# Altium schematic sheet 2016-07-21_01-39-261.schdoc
size 367 x 190 mm; SheetNumber: 1; SheetTotal: 1
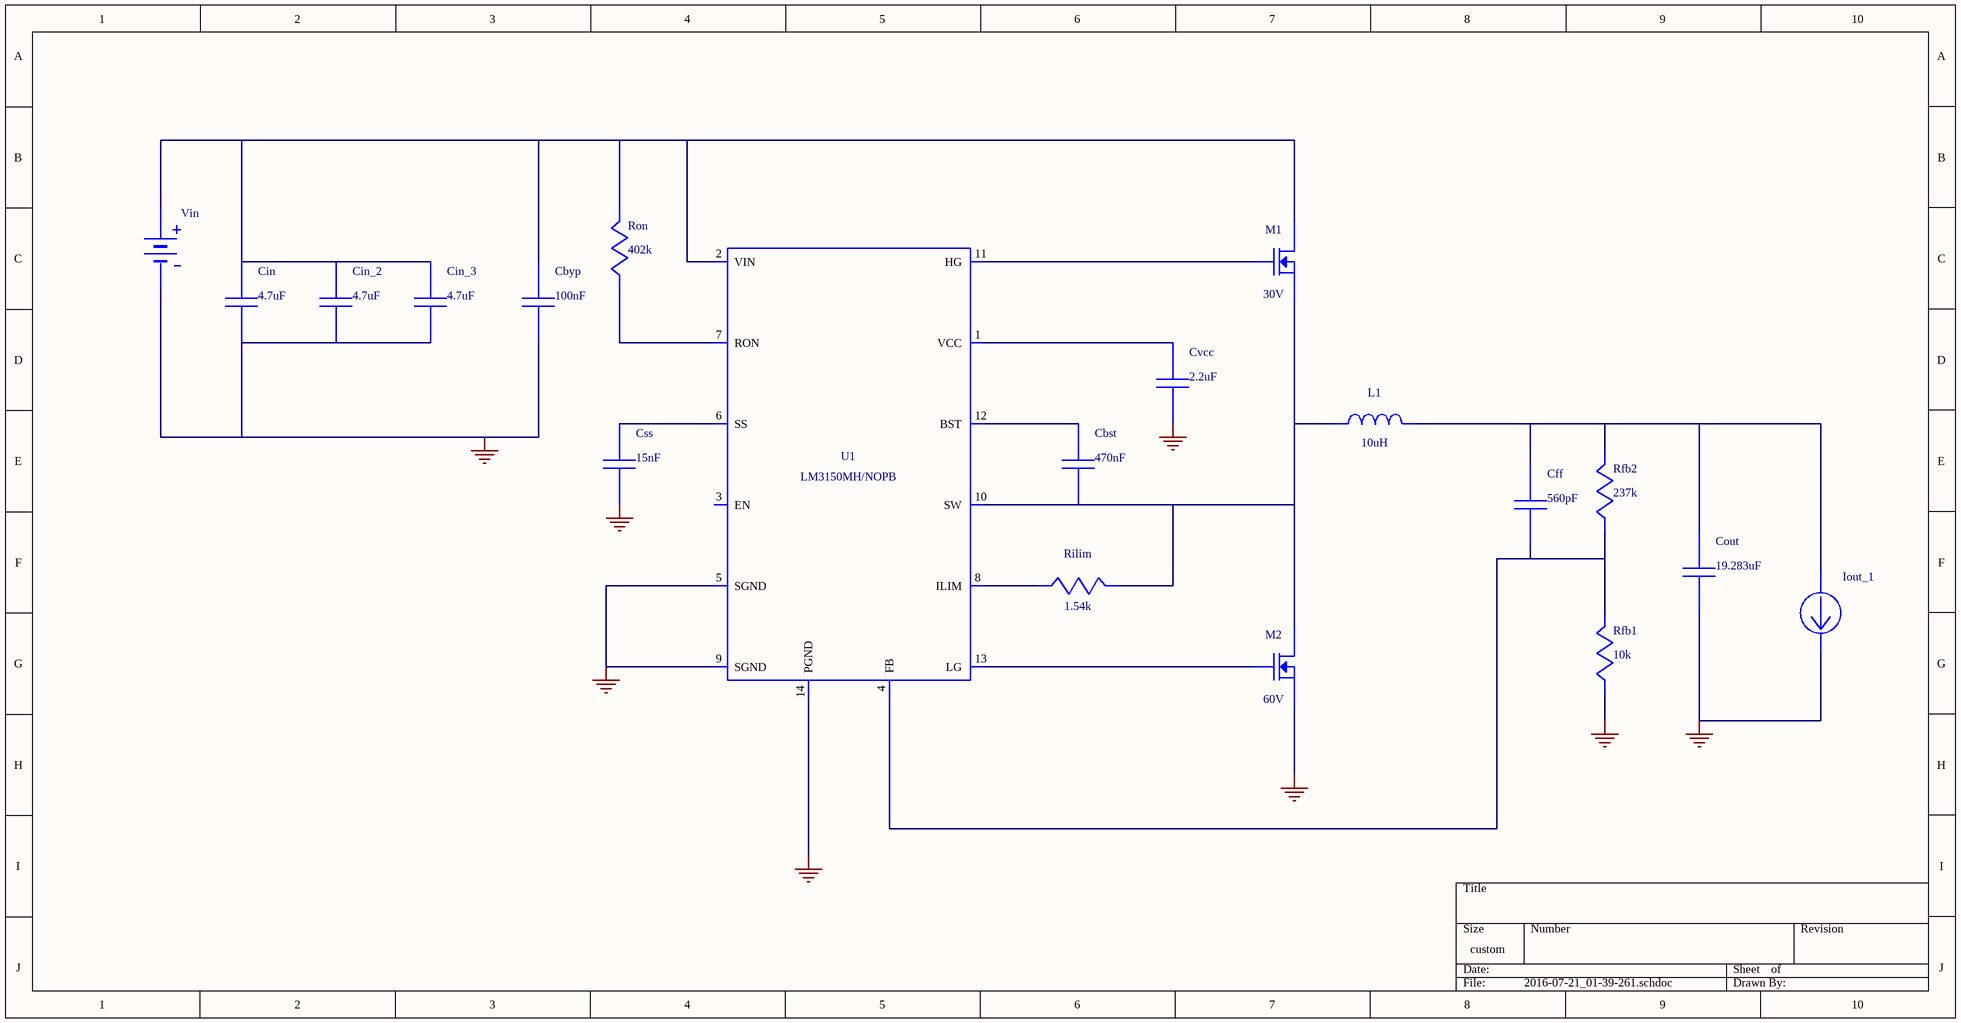
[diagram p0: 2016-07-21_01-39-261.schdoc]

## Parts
Cbst  value 470nF  (hidden comment: EMK212B7474KD-T)
Cbyp  value 100nF  (hidden comment: C0805C104K5RACTU)
Cff  value 560pF  (hidden comment: CC0805KRX7R9BB561)
Cin  value 4.7uF  (hidden comment: GRM31CR71H475KA12L)
Cin_2  value 4.7uF  (hidden comment: GRM31CR71H475KA12L)
Cin_3  value 4.7uF  (hidden comment: GRM31CR71H475KA12L)
Cout  value 19.283uF  (hidden comment: GENERIC_CAPACITOR)
Css  value 15nF  (hidden comment: CC0805KRX7R9BB153)
Cvcc  value 2.2uF  (hidden comment: EMK212B7225KG-T)
Iout_1  WB_CURRENT_LOAD  (value not drawn)
L1  value 10uH  (hidden comment: SRP1270-100M)
M1  value 30V  (hidden comment: CSD17307Q5A)
M2  value 60V  (hidden comment: CSD18537NQ5A)
Rfb1  value 10k  (hidden comment: ERJ-6ENF1002V)
Rfb2  value 237k  (hidden comment: ERJ-6ENF2373V)
Rilim  value 1.54k  (hidden comment: ERJ-6ENF1541V)
Ron  value 402k  (hidden comment: ERJ-6ENF4023V)
U1  LM3150MH/NOPB
Vin  WB_BATTERY  (value not drawn)

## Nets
0: Cbyp.2 Cin.2 Cin_2.2 Cin_3.2 Cout.2 Css.2 Cvcc.2 Iout_1.2(-) M2.1(Source) M2.2(Source) M2.3(Source) Rfb1.2 U1.5(SGND) U1.9(SGND) U1.14(PGND) U1.15(DAP) Vin.2(-)
NetCbst_1: Cbst.1 U1.12(BST)
NetCbst_2: Cbst.2 L1.1 M1.1(Source) M1.2(Source) M1.3(Source) M2.5(Drain) M2.6(Drain) M2.7(Drain) M2.8(Drain) M2.9(Drain) Rilim.1 U1.10(SW)
NetCbyp_1: Cbyp.1 Cin.1 Cin_2.1 Cin_3.1 M1.5(Drain) M1.6(Drain) M1.7(Drain) M1.8(Drain) M1.9(Drain) Ron.1 U1.2(VIN) Vin.1(+)
NetCff_1: Cff.1 Cout.1 Iout_1.1(+) L1.2 Rfb2.1
NetCff_2: Cff.2 Rfb1.1 Rfb2.2 U1.4(FB)
NetCss_1: Css.1 U1.6(SS)
NetCvcc_1: Cvcc.1 U1.1(VCC)
NetM1_4: M1.4(Gate) U1.11(HG)
NetM2_4: M2.4(Gate) U1.13(LG)
NetRilim_2: Rilim.2 U1.8(ILIM)
NetRon_2: Ron.2 U1.7(RON)

Not connected (* = marked no-connect by the designer): U1 3(EN)

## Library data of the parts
Cbst = EMK212B7474KD-T: Manufacturer Name: Taiyo Yuden
Cbyp = C0805C104K5RACTU: Manufacturer Name: Kemet
Cff = CC0805KRX7R9BB561: CC0805KRX7R9BB56; Manufacturer Name: Yageo America
Cin Cin_2 Cin_3 = GRM31CR71H475KA12L: GRM31CR71H475KA1; Manufacturer Name: MuRata
Cout = GENERIC_CAPACITOR: CUSTOM1; Manufacturer Name: CUSTOM
Css = CC0805KRX7R9BB153: CC0805KRX7R9BB15; Manufacturer Name: Yageo America
Cvcc = EMK212B7225KG-T: Manufacturer Name: Taiyo Yuden
L1 = SRP1270-100M: Manufacturer Name: Bourns
M1 = CSD17307Q5A: Manufacturer Name: Texas Instruments
M2 = CSD18537NQ5A: Manufacturer Name: Texas Instruments
Rfb1 = ERJ-6ENF1002V: Manufacturer Name: Panasonic
Rfb2 = ERJ-6ENF2373V: Manufacturer Name: Panasonic
Rilim = ERJ-6ENF1541V: Manufacturer Name: Panasonic
Ron = ERJ-6ENF4023V: Manufacturer Name: Panasonic
U1 = LM3150MH/NOPB: Manufacturer Name: Texas Instruments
